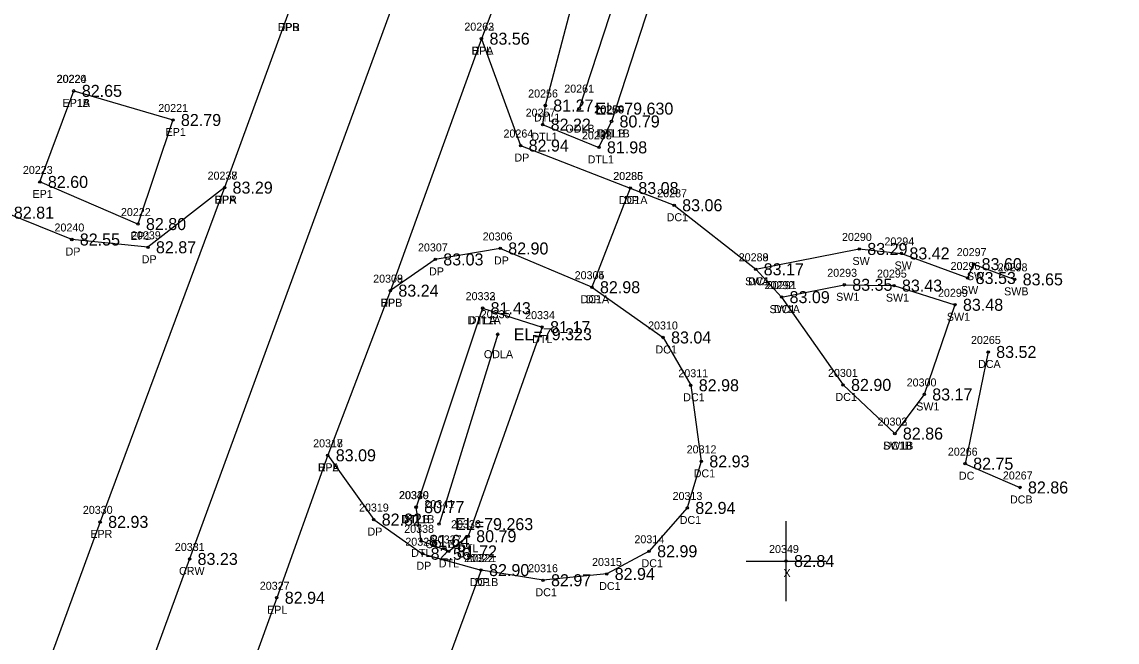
# Model space of a CAD drawing. Extents: x 2140110 to 2141565, y 506241 to 510327.
# Drawn here: x 2141166.2 to 2141303, y 509671 to 509748.5 of the extents above; entities that cross this region are included whole.
import ezdxf

# ---------------------------------------------------------------- set-up
doc = ezdxf.new("R2010")
doc.units = 0
for name, color, linetype in [('RD_DTM_BkLn1', 7, 'Continuous'), ('RD_EX_Conc', 7, 'Continuous'), ('RD_EX_Conc_txCode', 7, 'Continuous'), ('RD_EX_Driveway', 7, 'Continuous'), ('RD_EX_Driveway_txCode', 7, 'Continuous'), ('RD_EX_H2O', 7, 'Continuous'), ('RD_EX_H2O_txCode', 7, 'Continuous'), ('RD_EX_Misc', 7, 'Continuous'), ('RD_EX_Misc_txCode', 7, 'Continuous'), ('RD_EX_Road', 7, 'Continuous'), ('RD_EX_Road_txCode', 7, 'Continuous'), ('RD_EX_TX_Conc_ELEV', 7, 'Continuous'), ('RD_EX_TX_Driveway_ELEV', 7, 'Continuous'), ('RD_EX_TX_H2O_ELEV', 7, 'Continuous'), ('RD_EX_TX_Misc_ELEV', 7, 'Continuous'), ('RD_EX_TX_Road_ELEV', 7, 'Continuous'), ('RD_HC_Survey_ELEV', 7, 'Continuous'), ('RD_HC_Survey_txCode', 7, 'Continuous'), ('RD_SMD_Locator', 7, 'Continuous')]:
    doc.layers.add(name, color=color, linetype=linetype)

msp = doc.modelspace()

# ---------------------------------------------------------------- linework, layer by layer
at = {"layer": 'RD_DTM_BkLn1'}
msp.add_lwpolyline([(2141401.24, 510292.17), (2141386.62, 510241.55), (2141370.29, 510189.18), (2141352.34, 510135.64), (2141334.07, 510083.82), (2141314.82, 510031.25), (2141297.4, 509983.45), (2141260.01, 509880.66), (2141224.45, 509783.3), (2141187.1, 509681.41), (2141150.45, 509581.24), (2141112.96, 509478.26), (2141074.89, 509374.78), (2141038.89, 509276.46), (2141003.79, 509180.59), (2140969.89, 509087.8), (2140962.46, 509066.85), (2140921.91, 508956.12), (2140885.66, 508857.72), (2140850.55, 508762.05)], dxfattribs=at)
at = {"layer": 'RD_EX_Conc'}
for points in [[(2141242.15, 509727.75), (2141247.63, 509725.6), (2141257.81, 509717.6), (2141261.04, 509714.12), (2141268.72, 509703.15), (2141275.19, 509697.07)], [(2141257.81, 509717.6), (2141270.75, 509720.14), (2141276.01, 509719.58), (2141284.29, 509716.51), (2141285.03, 509718.24), (2141290.16, 509716.34)], [(2141237.36, 509715.36), (2141246.24, 509709.08), (2141249.7, 509703.11), (2141251.02, 509693.6), (2141249.27, 509687.78), (2141244.5, 509682.37), (2141239.2, 509679.53), (2141231.25, 509678.75), (2141223.51, 509680.02)], [(2141261.04, 509714.12), (2141268.87, 509715.66), (2141275.08, 509715.56), (2141282.7, 509713.16), (2141278.86, 509701.96), (2141275.19, 509697.07)], [(2141286.85, 509707.27), (2141283.97, 509693.31), (2141290.82, 509690.34)]]:
    msp.add_lwpolyline(points, dxfattribs=at)
at = {"layer": 'RD_EX_Driveway'}
for points in [[(2141223.56, 509746.41), (2141228.45, 509733.06), (2141242.15, 509727.75), (2141237.36, 509715.36), (2141225.9, 509720.2), (2141217.79, 509718.83), (2141212.18, 509714.93)], [(2141191.47, 509727.8), (2141181.9, 509720.35), (2141172.39, 509721.32), (2141164.15, 509724.67), (2141156.72, 509705.7), (2141152.41, 509694.43), (2141146.18, 509677.35), (2141143.5, 509670.11), (2141126.23, 509619.16), (2141121.57, 509618.23), (2141114.74, 509598.13), (2141140.09, 509588.3)], [(2141204.36, 509694.36), (2141210.1, 509686.33), (2141216.21, 509682.06), (2141223.51, 509680.02), (2141217.48, 509663.63), (2141210.53, 509667.64), (2141203.7, 509668.91), (2141193.66, 509664.6)]]:
    msp.add_lwpolyline(points, dxfattribs=at)
at = {"layer": 'RD_EX_H2O'}
for p, q in [((2141246.04, 509769.27), (2141235.76, 509737.67)), ((2141223.7, 509712.74), (2141215.4, 509687.88)), ((2141225.59, 509709.49), (2141218.26, 509685.76))]:
    msp.add_line(p, q, dxfattribs=at)
for points in [[(2141247.26, 509773.42), (2141240.68, 509772.91), (2141231.53, 509738.06), (2141231.2, 509735.67), (2141238.23, 509732.83), (2141239.8, 509736.07)], [(2141247.26, 509773.42), (2141250.66, 509769.48), (2141239.8, 509736.07)], [(2141223.7, 509712.74), (2141231.13, 509710.37), (2141221.9, 509684.25), (2141219.47, 509682.35), (2141216.02, 509683.67), (2141215.4, 509687.88)]]:
    msp.add_lwpolyline(points, dxfattribs=at)
at = {"layer": 'RD_EX_Misc'}
for p, q in [((2141261.6, 509676.15), (2141261.6, 509686.15)), ((2141256.6, 509681.15), (2141266.6, 509681.15))]:
    msp.add_line(p, q, dxfattribs=at)
at = {"layer": 'RD_EX_Road'}
for points in [[(2141389.23, 510293.58), (2141374.66, 510243.58), (2141359.1, 510192.72), (2141341.17, 510140.58), (2141322.74, 510087.97), (2141303.61, 510035.12), (2141287.18, 509990.16), (2141276.99, 509962.02), (2141248.91, 509884.35), (2141213.37, 509787.47), (2141207.76, 509772.94), (2141199.35, 509749.36), (2141191.47, 509727.8), (2141175.93, 509686.04), (2141140.09, 509588.3)], [(2141412.62, 510288.46), (2141398.29, 510238.16), (2141381.65, 510185.39), (2141379.05, 510176.51), (2141367.08, 510141.57), (2141363.58, 510131.95), (2141345.23, 510080.36), (2141326.05, 510027.03), (2141308.64, 509979.4), (2141271.24, 509876.37), (2141240, 509789.51), (2141233.78, 509773.43), (2141223.56, 509746.41), (2141212.18, 509714.93), (2141204.36, 509694.36), (2141197.99, 509676.56), (2141193.66, 509664.6)], [(2141172.64, 509739.89), (2141185.02, 509736.25), (2141180.65, 509723.25), (2141168.4, 509728.51), (2141172.64, 509739.89)]]:
    msp.add_lwpolyline(points, dxfattribs=at)
at = {"layer": 'RD_SMD_Locator'}
for centre in [(2141223.56, 509746.41), (2141223.56, 509746.41), (2141172.64, 509739.89), (2141172.64, 509739.89), (2141231.53, 509738.06), (2141235.76, 509737.67), (2141185.02, 509736.25), (2141231.2, 509735.67), (2141239.8, 509736.07), (2141239.8, 509736.07), (2141228.45, 509733.06), (2141238.23, 509732.83), (2141168.4, 509728.51), (2141191.47, 509727.8), (2141191.47, 509727.8), (2141242.15, 509727.75), (2141242.15, 509727.75), (2141247.63, 509725.6), (2141180.65, 509723.25), (2141172.39, 509721.32), (2141181.9, 509720.35), (2141225.9, 509720.2), (2141270.75, 509720.14), (2141217.79, 509718.83), (2141276.01, 509719.58), (2141257.81, 509717.6), (2141257.81, 509717.6), (2141285.03, 509718.24), (2141284.29, 509716.51), (2141290.16, 509716.34), (2141212.18, 509714.93), (2141212.18, 509714.93), (2141237.36, 509715.36), (2141237.36, 509715.36), (2141268.87, 509715.66), (2141275.08, 509715.56), (2141261.04, 509714.12), (2141261.04, 509714.12), (2141282.7, 509713.16), (2141223.7, 509712.74), (2141223.7, 509712.74), (2141231.13, 509710.37), (2141225.59, 509709.49), (2141246.24, 509709.08), (2141286.85, 509707.27), (2141249.7, 509703.11), (2141268.72, 509703.15), (2141278.86, 509701.96), (2141275.19, 509697.07), (2141275.19, 509697.07), (2141204.36, 509694.36), (2141204.36, 509694.36), (2141251.02, 509693.6), (2141283.97, 509693.31), (2141290.82, 509690.34), (2141215.4, 509687.88), (2141215.4, 509687.88), (2141249.27, 509687.78), (2141175.93, 509686.04), (2141210.1, 509686.33), (2141218.26, 509685.76), (2141216.02, 509683.67), (2141221.9, 509684.25), (2141216.21, 509682.06), (2141219.47, 509682.35), (2141244.5, 509682.37), (2141187.1, 509681.41), (2141261.6, 509681.15), (2141223.51, 509680.02), (2141223.51, 509680.02), (2141239.2, 509679.53), (2141231.25, 509678.75), (2141197.99, 509676.56)]:
    msp.add_circle(centre, 0.15, dxfattribs=at)

# ---------------------------------------------------------------- texts
at = {"layer": 'RD_EX_Conc_txCode'}
for s, p in [('20286', (2141240.01, 509728.75)), ('20287', (2141245.51, 509726.6)), ('DC1A', (2141240.72, 509725.75)), ('DC1', (2141246.69, 509723.6)), ('20290', (2141268.59, 509721.14)), ('20294', (2141273.89, 509720.58)), ('20297', (2141282.92, 509719.24)), ('20288', (2141255.69, 509718.6)), ('20289', (2141255.69, 509718.6)), ('SW', (2141269.9, 509718.14)), ('20305', (2141235.2, 509716.36)), ('20293', (2141266.75, 509716.66)), ('20295', (2141272.96, 509716.56)), ('SW', (2141275.16, 509717.58)), ('20296', (2141282.15, 509717.51)), ('20298', (2141288.04, 509717.34)), ('SWA', (2141256.48, 509715.6)), ('DC1', (2141256.86, 509715.6)), ('20292', (2141258.92, 509715.12)), ('20291', (2141259.2, 509715.12)), ('SW', (2141284.19, 509716.24)), ('SW1', (2141267.86, 509713.66)), ('20299', (2141280.58, 509714.16)), ('SW', (2141283.45, 509714.51)), ('SWB', (2141288.84, 509714.34)), ('DC1A', (2141235.93, 509713.36)), ('SW1', (2141274.07, 509713.56)), ('SW1A', (2141259.54, 509712.12)), ('DC1', (2141260.09, 509712.12)), ('SW1', (2141281.69, 509711.16)), ('20310', (2141244.37, 509710.08)), ('20265', (2141284.7, 509708.27)), ('DC1', (2141245.29, 509707.08)), ('20311', (2141248.15, 509704.11)), ('20301', (2141266.84, 509704.15)), ('DCA', (2141285.58, 509705.27)), ('20300', (2141276.67, 509702.96)), ('DC1', (2141248.76, 509701.11)), ('DC1', (2141267.77, 509701.15)), ('SW1', (2141277.86, 509699.96)), ('20302', (2141273.03, 509698.07)), ('20303', (2141273.03, 509698.07)), ('20312', (2141249.19, 509694.6)), ('SW1B', (2141273.71, 509695.07)), ('DC1B', (2141273.77, 509695.07)), ('20266', (2141281.81, 509694.31)), ('DC1', (2141250.07, 509691.6)), ('DC', (2141283.19, 509691.31)), ('20267', (2141288.68, 509691.34)), ('20313', (2141247.43, 509688.78)), ('DCB', (2141289.57, 509688.34)), ('DC1', (2141248.32, 509685.78)), ('20314', (2141242.66, 509683.37)), ('20322', (2141221.39, 509681.02)), ('20316', (2141229.39, 509679.75)), ('20315', (2141237.37, 509680.53)), ('DC1', (2141243.55, 509680.37)), ('DC1B', (2141222.09, 509678.02)), ('DC1', (2141230.3, 509676.75)), ('DC1', (2141238.26, 509677.53))]:
    msp.add_text(s, height=1, dxfattribs=at).set_placement(p)
at = {"layer": 'RD_EX_Driveway_txCode'}
for s, p in [('DPB', (2141198.1, 509747.36)), ('20263', (2141221.42, 509747.41)), ('DPA', (2141222.3, 509744.41)), ('20264', (2141226.31, 509734.06)), ('DP', (2141227.67, 509731.06)), ('20238', (2141189.35, 509728.8)), ('20285', (2141240.03, 509728.75)), ('DPA', (2141190.2, 509725.8)), ('DP', (2141241.37, 509725.75)), ('20240', (2141170.23, 509722.32)), ('20239', (2141179.78, 509721.35)), ('20306', (2141223.71, 509721.2)), ('DP', (2141171.61, 509719.32)), ('20307', (2141215.63, 509719.83)), ('DP', (2141181.12, 509718.35)), ('DP', (2141225.12, 509718.2)), ('DP', (2141217.01, 509716.83)), ('20304', (2141235.2, 509716.36)), ('20308', (2141210.03, 509715.93)), ('DPB', (2141210.93, 509712.93)), ('DP', (2141236.58, 509713.36)), ('20318', (2141202.53, 509695.36)), ('DPA', (2141203.1, 509692.36)), ('20319', (2141208.26, 509687.33)), ('DP', (2141209.32, 509684.33)), ('20320', (2141214.05, 509683.06)), ('20321', (2141221.67, 509681.02)), ('DP', (2141215.43, 509680.06)), ('DP', (2141222.73, 509678.02))]:
    msp.add_text(s, height=1, dxfattribs=at).set_placement(p)
at = {"layer": 'RD_EX_H2O_txCode'}
for s, p in [('20261', (2141233.9, 509739.67)), ('20256', (2141229.39, 509739.06)), ('20260', (2141237.62, 509737.07)), ('20259', (2141237.69, 509737.07)), ('20257', (2141229.08, 509736.67)), ('DTL1', (2141230.12, 509736.06)), ('ODLB', (2141234.04, 509734.67)), ('DTL1', (2141229.79, 509733.67)), ('20258', (2141236.11, 509733.83)), ('DTL1B', (2141237.92, 509734.07)), ('DTLB', (2141238.09, 509734.07)), ('DTL1', (2141236.82, 509730.83)), ('20332', (2141221.58, 509713.74)), ('20333', (2141221.58, 509713.74)), ('20335', (2141223.47, 509711.49)), ('20334', (2141229.01, 509711.37)), ('DTL1A', (2141221.8, 509710.74)), ('DTLA', (2141221.97, 509710.74)), ('DTL', (2141229.89, 509708.37)), ('ODLA', (2141223.86, 509706.49)), ('20340', (2141213.24, 509688.88)), ('20339', (2141213.28, 509688.88)), ('20341', (2141216.43, 509687.76)), ('DTL1B', (2141213.52, 509685.88)), ('DTLB', (2141213.68, 509685.88)), ('20336', (2141219.76, 509685.25)), ('20338', (2141213.91, 509684.67)), ('ODLB', (2141216.55, 509682.76)), ('20337', (2141217.35, 509683.35)), ('DTL', (2141220.65, 509682.25)), ('DTL', (2141214.78, 509681.67)), ('DTL', (2141218.22, 509680.35))]:
    msp.add_text(s, height=1, dxfattribs=at).set_placement(p)
at = {"layer": 'RD_EX_Misc_txCode'}
for s, p in [('20349', (2141259.48, 509682.15)), ('X', (2141261.28, 509679.15))]:
    msp.add_text(s, height=1, dxfattribs=at).set_placement(p)
at = {"layer": 'RD_EX_Road_txCode'}
for s, p in [('EPR', (2141198.12, 509747.36)), ('20262', (2141221.42, 509747.41)), ('EPL', (2141222.36, 509744.41)), ('20220', (2141170.48, 509740.89)), ('20224', (2141170.52, 509740.89)), ('EP1A', (2141171.23, 509737.89)), ('EP1B', (2141171.24, 509737.89)), ('20221', (2141183.19, 509737.25)), ('EP1', (2141184.1, 509734.25)), ('20223', (2141166.28, 509729.51)), ('20237', (2141189.35, 509728.8)), ('EP1', (2141167.48, 509726.51)), ('EPR', (2141190.24, 509725.8)), ('20222', (2141178.53, 509724.25)), ('EP1', (2141179.73, 509721.25)), ('20309', (2141210.03, 509715.93)), ('EPL', (2141210.98, 509712.93)), ('20317', (2141202.53, 509695.36)), ('EPL', (2141203.16, 509692.36)), ('20330', (2141173.77, 509687.04)), ('EPR', (2141174.7, 509684.04)), ('20327', (2141195.87, 509677.56)), ('EPL', (2141196.78, 509674.56))]:
    msp.add_text(s, height=1, dxfattribs=at).set_placement(p)
at = {"layer": 'RD_EX_TX_Conc_ELEV'}
for s, p in [('83.08', (2141243.15, 509727)), ('83.06', (2141248.63, 509724.85)), ('83.29', (2141271.75, 509719.39)), ('83.42', (2141277.01, 509718.83)), ('83.60', (2141286.03, 509717.49)), ('83.17', (2141258.81, 509716.85)), ('83.17', (2141258.81, 509716.85)), ('82.98', (2141238.36, 509714.61)), ('83.35', (2141269.87, 509714.91)), ('83.43', (2141276.08, 509714.81)), ('83.53', (2141285.29, 509715.76)), ('83.65', (2141291.16, 509715.59)), ('83.09', (2141262.04, 509713.37)), ('83.09', (2141262.04, 509713.37)), ('83.48', (2141283.7, 509712.41)), ('83.04', (2141247.24, 509708.33)), ('83.52', (2141287.85, 509706.52)), ('82.98', (2141250.7, 509702.36)), ('82.90', (2141269.72, 509702.4)), ('83.17', (2141279.86, 509701.21)), ('82.86', (2141276.19, 509696.32)), ('82.86', (2141276.19, 509696.32)), ('82.93', (2141252.02, 509692.85)), ('82.75', (2141284.97, 509692.56)), ('82.86', (2141291.82, 509689.59)), ('82.94', (2141250.27, 509687.03)), ('82.99', (2141245.5, 509681.62)), ('82.90', (2141224.51, 509679.27)), ('82.97', (2141232.25, 509678)), ('82.94', (2141240.2, 509678.78))]:
    msp.add_text(s, height=1.5, dxfattribs=at).set_placement(p)
at = {"layer": 'RD_EX_TX_Driveway_ELEV'}
for s, p in [('83.56', (2141224.56, 509745.66)), ('82.94', (2141229.45, 509732.31)), ('83.29', (2141192.47, 509727.05)), ('83.08', (2141243.15, 509727)), ('82.81', (2141165.15, 509723.92)), ('82.55', (2141173.39, 509720.57)), ('82.87', (2141182.9, 509719.6)), ('82.90', (2141226.9, 509719.45)), ('83.03', (2141218.79, 509718.08)), ('82.98', (2141238.36, 509714.61)), ('83.24', (2141213.18, 509714.18)), ('83.09', (2141205.36, 509693.61)), ('82.82', (2141211.1, 509685.58)), ('82.56', (2141217.21, 509681.31)), ('82.90', (2141224.51, 509679.27))]:
    msp.add_text(s, height=1.5, dxfattribs=at).set_placement(p)
at = {"layer": 'RD_EX_TX_H2O_ELEV'}
for s, p in [('81.27', (2141232.53, 509737.31)), ('EL=79.630', (2141237.76, 509736.92)), ('80.79', (2141240.8, 509735.32)), ('80.79', (2141240.8, 509735.32)), ('82.22', (2141232.2, 509734.92)), ('81.98', (2141239.23, 509732.08)), ('81.43', (2141224.7, 509711.99)), ('81.43', (2141224.7, 509711.99)), ('81.17', (2141232.13, 509709.62)), ('EL=79.323', (2141227.59, 509708.74)), ('80.77', (2141216.4, 509687.13)), ('80.77', (2141216.4, 509687.13)), ('EL=79.263', (2141220.26, 509685.01)), ('80.79', (2141222.9, 509683.5)), ('81.64', (2141217.02, 509682.92)), ('81.72', (2141220.47, 509681.6))]:
    msp.add_text(s, height=1.5, dxfattribs=at).set_placement(p)
at = {"layer": 'RD_EX_TX_Misc_ELEV'}
msp.add_text('82.84', height=1.5, dxfattribs=at).set_placement((2141262.6, 509680.4))
at = {"layer": 'RD_EX_TX_Road_ELEV'}
for s, p in [('83.56', (2141224.56, 509745.66)), ('82.65', (2141173.64, 509739.14)), ('82.65', (2141173.64, 509739.14)), ('82.79', (2141186.02, 509735.5)), ('82.60', (2141169.4, 509727.76)), ('83.29', (2141192.47, 509727.05)), ('82.80', (2141181.65, 509722.5)), ('83.24', (2141213.18, 509714.18)), ('83.09', (2141205.36, 509693.61)), ('82.93', (2141176.93, 509685.29)), ('82.94', (2141198.99, 509675.81))]:
    msp.add_text(s, height=1.5, dxfattribs=at).set_placement(p)
at = {"layer": 'RD_HC_Survey_ELEV'}
msp.add_text('83.23', height=1.5, dxfattribs=at).set_placement((2141188.1, 509680.66))
at = {"layer": 'RD_HC_Survey_txCode'}
for s, p in [('20331', (2141185.26, 509682.41)), ('CRW', (2141185.78, 509679.41))]:
    msp.add_text(s, height=1, dxfattribs=at).set_placement(p)

doc.saveas('drawing.dxf')
